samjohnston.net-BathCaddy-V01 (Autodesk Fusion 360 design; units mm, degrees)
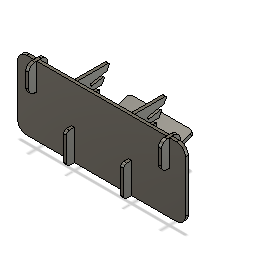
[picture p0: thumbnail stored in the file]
sketch "Sketch1" plane through (0, 0, 0) normal (0, 0, 1) x axis (1, 0, 0)
  line L1 (-340, 0) -> (0, 0)
  line L2 (-340, 280) -> (-340, 0)
  line L3 (0, 280) -> (-340, 280)
  line L4 (0, 0) -> (0, 280)
  line L5 (-122, 60) -> (-122, 0)
  line L6 (-110, 60) -> (-122, 60)
  line L7 (-110, 0) -> (-110, 60)
  line L8 (-275, 250) -> (-275, 280)
  line L9 (-263, 250) -> (-275, 250)
  line L10 (-263, 280) -> (-263, 250)
  line L11 (-275, 220) -> (-275, 250)
  line L12 (-263, 220) -> (-275, 220)
  line L13 (-263, 250) -> (-263, 220)
  line L14 (-134, 141.0354) -> (-328, 141.0354)
  line L15 (-134, 12) -> (-134, 141.0354)
  line L16 (-328, 12) -> (-134, 12)
  line L17 (-328, 141.0354) -> (-328, 12)
  line L18 (-340, 141.0354) -> (-328, 141.0354)
  line L19 (-109.5, 0) -> (-110, 3)
  line L20 (-122.5, 0) -> (-122, 3)
  line L21 (-122, 3) -> (-110, 3)
  line L22 (-263, 277) -> (-262.5, 280)
  line L23 (-275.5, 280) -> (-275, 277)
  line L24 (-263, 277) -> (-275, 277)
  line L25 (-269, 141.0354) -> (-269, 220)
  circle C1 centre (-269, 177.0354) radius 40
  point P1 (0, 0)
  point P2 (0, 0)
  point P6 (-122, 0)
  point P9 (-110, 0)
  point P10 (-275, 280)
  point P13 (-263, 280)
  point P21 (-340, 141.0354)
  point P22 (-110, 3)
  point P23 (-109.5, 0)
  point P24 (-122, 3)
  point P25 (-122.5, 0)
  point P26 (-262.5, 280)
  point P27 (-263, 277)
  point P28 (-275, 277)
  point P29 (-275.5, 280)
  point P30 (-269, 220)
  point P31 (-269, 141.0354)
  point P20 (-269, 177.0354)
  point P4 (-340, 280)
  point P5 (0, 280)
  point P3 (-340, 0)
  point P7 (-122, 60)
  point P8 (-110, 60)
  point P11 (-275, 250)
  point P12 (-263, 250)
  point P14 (-275, 220)
  point P16 (-328, 141.0354)
  point P19 (-328, 12)
  horizontal L1
  vertical L2
  horizontal L3
  vertical L4
  coincident P1 P2
  coincident L1 P6
  perpendicular L1 L5
  perpendicular L5 L6
  coincident L1 P9
  perpendicular L1 L7
  coincident L3 P10
  perpendicular L3 L8
  perpendicular L8 L9
  coincident L3 P13
  perpendicular L3 L10
  perpendicular L9 L11
  perpendicular L8 L12
  vertical L13
  horizontal L14
  vertical L15
  horizontal L16
  vertical L17
  coincident L2 P21
  horizontal L18
  coincident L7 P22
  coincident L1 P23
  coincident L5 P24
  coincident L1 P25
  coincident L3 P26
  coincident L10 P27
  coincident L8 P28
  coincident L3 P29
  perpendicular L8 L24
  horizontal L21
  midpoint L12 P30
  coincident L14 P31
  perpendicular L14 L25
  coincident P20 L25
  dimension "d1" distance P4 P5 = 340
  dimension "d2" distance P3 P4 = 280
  dimension "d4" distance P7 P8 = 12
  dimension "d5" distance P8 P9 = 60
  dimension "d7" distance P11 P12 = 12
  dimension "d8" distance P10 P11 = 30
  dimension "d9" distance L4 L8 = 275
  dimension "d10" distance L4 L7 = 110
  dimension "d11" distance P11 P14 = 30
  dimension "d12" distance L2 L17 = 12
  dimension "d14" distance L1 L16 = 12
  dimension "d15" distance L5 L15 = 12
  dimension "d74" diameter C1 = 80
  dimension "d83" distance L10 P26 = 0.5
  dimension "d84" distance P10 P29 = 0.5
  dimension "d85" distance L3 L24 = 3
  dimension "d86" distance L7 P23 = 0.5
  dimension "d87" distance P6 P25 = 0.5
  dimension "d88" distance L1 L21 = 3
  dimension "d108" distance P16 P19 = 129.0354
  dimension "d109" distance L14 P20 = 36
extrude "Extrude1" new body sketch "Sketch1" profile of L1 L2 L3 L4 L5 L6 L7 L8 L9 L10 L11 L12 L13 L14 L15 L16 L17 C1 L18 L19 L20 L22 L23 along normal blind 12 bodies "Platform"
extrude "Extrude8" add sketch "Sketch1" profile of L14 L15 L16 L17 C1 to an object from offset 2
fillet "Fillet1" radius 24 bodies "DeviceHolder1"
fillet "Fillet2" radius 36 bodies "DeviceHolder1"
sketch "Sketch3" plane through (0, 0, 0) normal (1, 0, 0) x axis (0, 0, -1)
  line L1 (0, 3) -> (0, 60)
  line L2 (0, 60) -> (-12, 60)
  line L3 (0, 250) -> (0, 277)
  line L4 (-12, 250) -> (0, 250)
  line L5 (-12, 277) -> (-12, 250)
  line L6 (0, 190) -> (0, 250)
  line L7 (32, 220) -> (0, 220)
  line L8 (32, 280) -> (32, 220)
  line L9 (0, 280) -> (32, 280)
  line L10 (-12, 60) -> (-12, 250)
  line L11 (-44, 172) -> (-12, 172)
  line L12 (-44, 280) -> (-44, 172)
  line L13 (-12, 280) -> (-44, 280)
  line L14 (0, 225) -> (0.5, 220)
  line L15 (-12, 177) -> (-12.5, 172)
  line L16 (-12, 3) -> (0, 3)
  line L17 (0, 277) -> (-12, 277)
  line L18 (-12, 280) -> (0, 280)
  line L19 (0, 280) -> (0, 0)
  point P7 (0, 250)
  point P10 (0, 250)
  point P8 (-12, 250)
  point P15 (-12, 250)
  point P5 (-12, 60)
  point P16 (-12, 60)
  point P21 (0.5, 220)
  point P23 (-12.5, 172)
  point P14 (0, 280)
  point P25 (0, 280)
  point P24 (-12, 177)
  point P17 (-12, 172)
  point P11 (0, 220)
  point P22 (0, 225)
  point P30 (0, 220)
  point P13 (32, 280)
  point P19 (-44, 280)
  point P20 (-12, 280)
  coincident P7 P10
  perpendicular L4 L6
  perpendicular L6 L7
  coincident P8 P15
  coincident P5 P16
  perpendicular L11 L12
  horizontal L13
  horizontal L9
  vertical L8
  coincident L7 P21
  coincident L11 P23
  coincident P14 P25
  coincident L10 P24
  coincident L10 P17
  horizontal L11
  coincident P11 L19
  coincident P22 L19
  coincident P11 P30
  dimension "d25" distance P13 P14 = 32
  dimension "d26" distance P19 P20 = 32
  dimension "d75" distance P17 P23 = 0.5
  dimension "d77" distance P11 P21 = 0.5
  dimension "d78" distance L7 P22 = 5
  dimension "d110" distance L11 P24 = 5
  dimension "d111" distance L7 L11 = 48
extrude "Extrude2" sketch "Sketch3" profile of L3 L4 L5 L6 L7 L8 L9 L10 L11 L12 L13 L14 L15 L17 L18 L19 blind -12 bodies "EndStop1"
fillet "Fillet3" radius 24 bodies "DeviceHolder1"
fillet "Fillet9" radius 2 bodies "DeviceHolder1"
sketch "Sketch4" plane through (0, 0, 0) normal (1, 0, 0) x axis (0, 0, -1)
  line L1 (0, 3) -> (0, 60)
  line L2 (-12, 60) -> (-12, 0)
  line L3 (0, 60) -> (-12, 60)
  line L4 (24, 0) -> (0, 0)
  line L5 (65.4939, 96.4469) -> (74.9501, 89.0589)
  line L6 (40.7734, 64.806) -> (65.4939, 96.4469)
  line L7 (24, 75.6988) -> (40.7734, 64.806)
  line L8 (132.6289, 280) -> (24, 75.6988)
  line L9 (0, 280) -> (132.6289, 280)
  line L10 (0, 60) -> (0, 280)
  line L11 (-44, 0) -> (-12, 0)
  line L12 (-44, 124) -> (-44, 0)
  line L13 (-12, 124) -> (-44, 124)
  line L14 (-12, 60) -> (-12, 124)
  line L15 (49.6788, 14.8256) -> (74.9501, 89.0589)
  line L16 (24, 0) -> (49.6788, 14.8256)
  line L17 (33.4184, 206.2559) -> (93.4184, 206.2559)
  line L18 (33.4184, 217.2559) -> (33.4184, 206.2559)
  line L19 (99.2672, 217.2559) -> (33.4184, 217.2559)
  line L20 (54.2259, 233.2559) -> (113.3144, 243.6748)
  line L21 (52.3158, 244.0888) -> (54.2259, 233.2559)
  line L22 (119.8678, 256) -> (52.3158, 244.0888)
  line L23 (16.5323, 179.2977) -> (76.304, 174.0684)
  line L24 (17.4911, 190.2559) -> (16.5323, 179.2977)
  line L25 (81.9142, 184.6196) -> (17.4911, 190.2559)
  line L26 (28.1042, 24) -> (56.295, 34.2606)
  line L27 (24, 35.2763) -> (28.1042, 24)
  line L28 (61.2572, 48.8368) -> (24, 35.2763)
  line L29 (56.2123, 34.0177) -> (28.1042, 24)
  line L30 (61.3399, 49.0798) -> (24, 35.2763)
  line L31 (24, 75.6988) -> (24, 0)
  line L32 (-12.5, 124) -> (-12, 121)
  line L33 (0, 277) -> (0.5, 280)
  line L34 (-12, 3) -> (0, 3)
  line L35 (0, 0) -> (-12, 0)
  line L36 (0, 3) -> (0, 0)
  point P2 (0, 60)
  point P14 (0, 60)
  point P5 (-12, 60)
  point P19 (-12, 60)
  point P21 (93.4184, 206.2559)
  point P24 (99.2672, 217.2559)
  point P25 (113.3144, 243.6748)
  point P28 (119.8678, 256)
  point P29 (76.304, 174.0684)
  point P32 (81.9142, 184.6196)
  point P33 (56.295, 34.2606)
  point P36 (61.2572, 48.8368)
  point P37 (56.2123, 34.0177)
  point P38 (61.3399, 49.0798)
  point P35 (24, 35.2763)
  point P13 (0, 280)
  point P39 (0, 280)
  point P40 (-12, 121)
  point P41 (-12.5, 124)
  point P42 (0.5, 280)
  point P43 (0, 277)
  point P1 (0, 0)
  point P6 (0, 0)
  point P44 (0, 0)
  point P3 (0, 3)
  point P45 (0, 3)
  point P10 (40.7734, 64.806)
  point P11 (24, 75.6988)
  point P8 (74.9501, 89.0589)
  point P9 (65.4939, 96.4469)
  point P30 (16.5323, 179.2977)
  point P31 (17.4911, 190.2559)
  point P22 (33.4184, 206.2559)
  point P23 (33.4184, 217.2559)
  point P26 (54.2259, 233.2559)
  point P27 (52.3158, 244.0888)
  point P15 (-12, 0)
  point P16 (-44, 0)
  point P18 (-12, 124)
  point P34 (28.1042, 24)
  point P20 (49.6788, 14.8256)
  perpendicular L5 L6
  parallel L3 L9
  coincident P2 P14
  perpendicular L3 L10
  perpendicular L2 L11
  perpendicular L11 L12
  perpendicular L2 L13
  coincident P5 P19
  perpendicular L3 L14
  horizontal L4
  coincident L8 P21
  horizontal L17
  perpendicular L17 L18
  coincident L8 P24
  perpendicular L18 L19
  coincident L8 P25
  perpendicular L20 L21
  coincident L8 P28
  perpendicular L21 L22
  coincident L8 P29
  perpendicular L23 L24
  coincident L8 P32
  perpendicular L24 L25
  coincident L15 P33
  perpendicular L26 L27
  coincident L15 P36
  perpendicular L27 L28
  coincident L15 P37
  coincident L15 P38
  vertical L31
  coincident P35 L31
  coincident P13 P39
  coincident L14 P40
  coincident L13 P41
  coincident L9 P42
  coincident L10 P43
  coincident P1 P6
  coincident P1 P44
  horizontal L35
  coincident P3 P45
  dimension "d33" distance P10 P11 = 20
  dimension "d34" angle L6 L7 = 95
  dimension "d35" angle L7 L8 = 95
  dimension "d36" angle L8 L10 = 28
  dimension "d38" distance P8 P9 = 12
  dimension "d39" distance P9 L7 = 40
  dimension "d40" distance L1 P11 = 24
  dimension "d41" angle L17 L25 = 5
  dimension "d42" angle L19 L20 = 10
  dimension "d43" distance P30 P31 = 11
  dimension "d44" distance P22 P23 = 11
  dimension "d45" distance P26 P27 = 11
  dimension "d46" distance P21 P22 = 60
  dimension "d47" distance P29 P30 = 60
  dimension "d48" distance P25 P26 = 60
  dimension "d49" distance L17 P31 = 16
  dimension "d50" distance L19 P26 = 16
  dimension "d51" distance P15 P16 = 32
  dimension "d52" distance P18 P19 = 64
  dimension "d54" distance L26 P37 = 0.2
  dimension "d55" distance L28 P38 = 0.2
  dimension "d56" distance P34 P35 = 12
  dimension "d59" angle L28 L31 = 70
  dimension "d60" distance P20 L26 = 16
  dimension "d61" angle L16 L31 = 60
  dimension "d62" distance P33 P34 = 30
  dimension "d63" distance L4 P34 = 24
  dimension "d64" distance L9 P28 = 24
  dimension "d79" distance L10 P42 = 0.5
  dimension "d80" distance L14 P41 = 0.5
  dimension "d81" distance L13 P40 = 3
  dimension "d82" distance P42 P43 = 3
extrude "Extrude3" sketch "Sketch4" profile of L1 L2 L3 L4 L5 L6 L7 L8 L9 L10 L11 L12 L13 L14 L15 L16 L17 L18 L19 L20 L21 L22 L23 L24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 blind -12 bodies "DeviceHolder1"
fillet "Fillet4" radius 12 bodies "DeviceHolder1"
fillet "Fillet5" radius 5 bodies "DeviceHolder1"
fillet "Fillet6" radius 4 bodies "DeviceHolder1"
sketch "Sketch5" plane through (0, 0, 0) normal (1, 0, 0) x axis (0, 0, -1)
  line L1 (28.1042, 24) -> (56.295, 34.2606)
  line L2 (61.2572, 48.8368) -> (24, 35.2763)
  line L3 (28.1042, 24) -> (24, 35.2763)
  line L4 (234.8366, 99.2444) -> (56.295, 34.2606)
  line L5 (230.7324, 110.5207) -> (234.8366, 99.2444)
  line L6 (61.2572, 48.8368) -> (230.7324, 110.5207)
  line L7 (83.9952, -30.1498) -> (50.4772, 61.9401)
  line L8 (72.7189, -34.254) -> (83.9952, -30.1498)
  line L9 (39.2009, 57.8358) -> (72.7189, -34.254)
  line L10 (50.4772, 61.9401) -> (39.2009, 57.8358)
  point P4 (24, 35.2763)
  point P6 (24, 35.2763)
  point P3 (28.1042, 24)
  point P7 (28.1042, 24)
  point P2 (56.295, 34.2606)
  point P8 (56.295, 34.2606)
  point P5 (61.2572, 48.8368)
  point P11 (61.2572, 48.8368)
  point P12 (50.4772, 61.9401)
  point P15 (39.2009, 57.8358)
  coincident P4 P6
  coincident P3 P7
  coincident P2 P8
  perpendicular L3 L4
  perpendicular L1 L5
  coincident P5 P11
  collinear L2 L6
  perpendicular L6 L7
  perpendicular L7 L8
  perpendicular L2 L9
  perpendicular L9 L10
  dimension "d89" distance L3 L5 = 220
  dimension "d90" distance P12 P15 = 12
  dimension "d91" distance L3 L9 = 22
  dimension "d92" distance L2 L10 = 16
  dimension "d93" distance L4 L8 = 70
extrude "Extrude4" new body sketch "Sketch5" profile of L1 L2 L3 L4 L5 L6 L7 L9 against normal blind 130
extrude "Extrude5" cut sketch "Sketch5" profile of L2 L4 L6 L7 L9 against normal blind 60
extrude "Extrude6" new body sketch "Sketch5" profile of L2 L4 L6 L7 L9 L10 to an object bodies "BookPlatformLip"
extrude "Extrude7" new body sketch "Sketch5" profile of L1 L4 L7 L8 L9 against normal blind 100
mirror "Mirror1" mirrorStitchTolerance 0.1 bodies "EndStop2", "DeviceHolder2", "BookPlatform"
combine "Combine1"
combine "Combine2"
combine "Combine3"
fillet "Fillet7" radius 12 bodies "DeviceHolder1"
fillet "Fillet8" radius 4 bodies "DeviceHolder1"
sketch "BB-Platform-V01" plane through (0, 0, 0) normal (0, 0, -1) x axis (-1, 0, 0)
  line L1 (-304, 12) -> (-158, 12)
  line L2 (-328, 117.0354) -> (-328, 36)
  line L3 (-158, 141.0354) -> (-244.3423, 141.0354)
  line L4 (-134, 36) -> (-134, 117.0354)
  line L5 (134, 117.0354) -> (134, 36)
  line L6 (304, 141.0354) -> (293.6577, 141.0354)
  line L7 (328, 36) -> (328, 117.0354)
  line L8 (158, 12) -> (304, 12)
  line L9 (275.5, 280) -> (304, 280)
  line L10 (275, 277) -> (275.5, 280)
  line L11 (275, 250) -> (275, 277)
  line L12 (263, 250) -> (275, 250)
  line L13 (263, 277) -> (263, 250)
  line L14 (262.5, 280) -> (263, 277)
  line L15 (-262.5, 280) -> (262.5, 280)
  line L16 (-263, 277) -> (-262.5, 280)
  line L17 (-263, 250) -> (-263, 277)
  line L18 (-275, 250) -> (-263, 250)
  line L19 (-275, 277) -> (-275, 250)
  line L20 (-275.5, 280) -> (-275, 277)
  line L21 (-304, 280) -> (-275.5, 280)
  line L22 (-340, 36) -> (-340, 244)
  line L23 (-122.5, 0) -> (-304, 0)
  line L24 (-122, 3) -> (-122.5, 0)
  line L25 (-122, 60) -> (-122, 3)
  line L26 (-110, 60) -> (-122, 60)
  line L27 (-110, 3) -> (-110, 60)
  line L28 (-109.5, 0) -> (-110, 3)
  line L29 (109.5, 0) -> (-109.5, 0)
  line L30 (110, 3) -> (109.5, 0)
  line L31 (110, 60) -> (110, 3)
  line L32 (122, 60) -> (110, 60)
  line L33 (122, 3) -> (122, 60)
  line L34 (122.5, 0) -> (122, 3)
  line L35 (304, 0) -> (122.5, 0)
  line L36 (340, 244) -> (340, 36)
  line L37 (-293.6577, 141.0354) -> (-304, 141.0354)
  line L38 (244.3423, 141.0354) -> (158, 141.0354)
  arc A1 centre (-158, 36) radius 24 clockwise from (-134, 36) to (-158, 12)
  arc A2 centre (-304, 36) radius 24 clockwise from (-304, 12) to (-328, 36)
  arc A3 centre (-304, 117.0354) radius 24 clockwise from (-328, 117.0354) to (-304, 141.0354)
  arc A4 centre (-158, 117.0354) radius 24 clockwise from (-158, 141.0354) to (-134, 117.0354)
  arc A5 centre (158, 36) radius 24 clockwise from (158, 12) to (134, 36)
  arc A6 centre (158, 117.0354) radius 24 clockwise from (134, 117.0354) to (158, 141.0354)
  arc A7 centre (304, 117.0354) radius 24 clockwise from (304, 141.0354) to (328, 117.0354)
  arc A8 centre (304, 36) radius 24 clockwise from (328, 36) to (304, 12)
  arc A9 centre (304, 244) radius 36 clockwise from (304, 280) to (340, 244)
  arc A10 centre (-304, 244) radius 36 clockwise from (-340, 244) to (-304, 280)
  arc A11 centre (-304, 36) radius 36 clockwise from (-304, 0) to (-340, 36)
  arc A12 centre (304, 36) radius 36 clockwise from (340, 36) to (304, 0)
  arc A13 centre (-269, 177.0354) radius 40 clockwise from (-292.4835, 144.6544) to (-245.5165, 144.6544)
  arc A14 centre (269, 177.0354) radius 40 clockwise from (245.5165, 144.6544) to (292.4835, 144.6544)
  arc A15 centre (-293.6577, 143.0354) radius 2 clockwise from (-292.4835, 144.6544) to (-293.6577, 141.0354)
  arc A16 centre (-244.3423, 143.0354) radius 2 clockwise from (-244.3423, 141.0354) to (-245.5165, 144.6544)
  arc A17 centre (293.6577, 143.0354) radius 2 clockwise from (293.6577, 141.0354) to (292.4835, 144.6544)
  arc A18 centre (244.3423, 143.0354) radius 2 clockwise from (245.5165, 144.6544) to (244.3423, 141.0354)
sketch "BB-Stop-V01" plane through (275, 0, 0) normal (1, 0, 0) x axis (0, 0, -1)
  line L1 (0, 225) -> (0, 250)
  line L2 (8, 220) -> (0.5, 220)
  line L3 (0.5, 220) -> (0, 225)
  line L4 (0, 250) -> (-12, 250)
  line L5 (32, 256) -> (32, 244)
  line L6 (-20, 280) -> (8, 280)
  line L7 (-12, 172) -> (-20, 172)
  line L8 (-12, 250) -> (-12, 172)
  line L9 (-44, 196) -> (-44, 256)
  arc A1 centre (8, 244) radius 24 clockwise from (32, 244) to (8, 220)
  arc A2 centre (8, 256) radius 24 clockwise from (8, 280) to (32, 256)
  arc A3 centre (-20, 196) radius 24 clockwise from (-20, 172) to (-44, 196)
  arc A4 centre (-20, 256) radius 24 clockwise from (-44, 256) to (-20, 280)
sketch "BB-Holder-V01" plane through (122, 0, 0) normal (1, 0, 0) x axis (0, 0, -1)
  line L1 (0.5, 280) -> (125.9717, 280)
  line L2 (0, 277) -> (0.5, 280)
  line L3 (0, 60) -> (0, 277)
  line L4 (-12, 60) -> (0, 60)
  line L5 (-12, 121) -> (-12, 60)
  line L6 (-12.5, 124) -> (-12, 121)
  line L7 (-32, 124) -> (-12.5, 124)
  line L8 (-44, 12) -> (-44, 112)
  line L9 (20.7846, 0) -> (-32, 0)
  line L10 (45.7726, 12.5704) -> (26.7846, 1.6077)
  line L11 (53.5448, 26.1819) -> (51.1323, 19.0955)
  line L12 (28.1042, 24) -> (48.4153, 31.2388)
  line L13 (24, 35.2763) -> (28.1042, 24)
  line L14 (59.5539, 48.4195) -> (24, 35.2763)
  line L15 (74.034, 86.3679) -> (61.9536, 50.8823)
  line L16 (68.646, 93.9842) -> (72.71, 90.8091)
  line L17 (43.5942, 68.4164) -> (63.0313, 93.2948)
  line L18 (27.8425, 73.2035) -> (36.9309, 67.3014)
  line L19 (73.4668, 168.7324) -> (26.151, 79.7442)
  line L20 (20.5171, 178.9491) -> (70.2837, 174.5951)
  line L21 (17.1424, 186.2711) -> (16.881, 183.2825)
  line L22 (79.2767, 184.8503) -> (21.4758, 189.9072)
  line L23 (90.2931, 200.378) -> (83.1571, 186.9572)
  line L24 (37.4184, 206.2559) -> (86.7613, 206.2559)
  line L25 (33.4184, 213.2559) -> (33.4184, 210.2559)
  line L26 (96.8638, 217.2559) -> (37.4184, 217.2559)
  line L27 (109.4642, 236.4335) -> (100.3956, 219.378)
  line L28 (58.1652, 233.9505) -> (105.2378, 242.2506)
  line L29 (53.0104, 240.1495) -> (53.5313, 237.1951)
  line L30 (117.9465, 255.6612) -> (56.255, 244.7833)
  line L31 (129.5035, 274.1221) -> (120.7837, 257.7226)
  arc A1 centre (125.9717, 276) radius 4 clockwise from (125.9717, 280) to (129.5035, 274.1221)
  arc A2 centre (-32, 112) radius 12 clockwise from (-44, 112) to (-32, 124)
  arc A3 centre (-32, 12) radius 12 clockwise from (-32, 0) to (-44, 12)
  arc A4 centre (20.7846, 12) radius 12 clockwise from (26.7846, 1.6077) to (20.7846, 0)
  arc A5 centre (39.7726, 22.9627) radius 12 clockwise from (51.1323, 19.0955) to (45.7726, 12.5704)
  arc A6 centre (49.7582, 27.471) radius 4 clockwise from (48.4153, 31.2388) to (53.5448, 26.1819)
  arc A7 centre (58.167, 52.1714) radius 4 clockwise from (61.9536, 50.8823) to (59.5539, 48.4195)
  arc A8 centre (70.2474, 87.657) radius 4 clockwise from (72.71, 90.8091) to (74.034, 86.3679)
  arc A9 centre (66.1833, 90.8322) radius 4 clockwise from (63.0313, 93.2948) to (68.646, 93.9842)
  arc A10 centre (39.6541, 71.4947) radius 5 clockwise from (43.5942, 68.4164) to (36.9309, 67.3014)
  arc A11 centre (30.5657, 77.3968) radius 5 clockwise from (27.8425, 73.2035) to (26.151, 79.7442)
  arc A12 centre (69.9351, 170.6103) radius 4 clockwise from (70.2837, 174.5951) to (73.4668, 168.7324)
  arc A13 centre (20.8657, 182.9339) radius 4 clockwise from (20.5171, 178.9491) to (16.881, 183.2825)
  arc A14 centre (21.1272, 185.9225) radius 4 clockwise from (17.1424, 186.2711) to (21.4758, 189.9072)
  arc A15 centre (79.6253, 188.8351) radius 4 clockwise from (83.1571, 186.9572) to (79.2767, 184.8503)
  arc A16 centre (86.7613, 202.2559) radius 4 clockwise from (86.7613, 206.2559) to (90.2931, 200.378)
  arc A17 centre (37.4184, 210.2559) radius 4 clockwise from (37.4184, 206.2559) to (33.4184, 210.2559)
  arc A18 centre (37.4184, 213.2559) radius 4 clockwise from (33.4184, 213.2559) to (37.4184, 217.2559)
  arc A19 centre (96.8638, 221.2559) radius 4 clockwise from (100.3956, 219.378) to (96.8638, 217.2559)
  arc A20 centre (105.9324, 238.3114) radius 4 clockwise from (105.2378, 242.2506) to (109.4642, 236.4335)
  arc A21 centre (57.4706, 237.8897) radius 4 clockwise from (58.1652, 233.9505) to (53.5313, 237.1951)
  arc A22 centre (56.9496, 240.8441) radius 4 clockwise from (53.0104, 240.1495) to (56.255, 244.7833)
  arc A23 centre (117.252, 259.6005) radius 4 clockwise from (120.7837, 257.7226) to (117.9465, 255.6612)
sketch "BB-Book-V01" plane through (0, 12.16, 4.4259) normal (0, -0.9397, -0.342) x axis (-1, 0, 0)
  line L1 (130, 242.6178) -> (130, 38.6178)
  line L2 (-118, 254.6178) -> (118, 254.6178)
  line L3 (-130, 38.6178) -> (-130, 242.6178)
  line L4 (126, 34.6178) -> (-126, 34.6178)
  line L5 (-60, 56.6178) -> (60, 56.6178)
  line L6 (-60, 68.6178) -> (-60, 56.6178)
  line L7 (60, 68.6178) -> (-60, 68.6178)
  line L8 (60, 56.6178) -> (60, 68.6178)
  arc A1 centre (126, 38.6178) radius 4 clockwise from (130, 38.6178) to (126, 34.6178)
  arc A2 centre (118, 242.6178) radius 12 clockwise from (118, 254.6178) to (130, 242.6178)
  arc A3 centre (-118, 242.6178) radius 12 clockwise from (-130, 242.6178) to (-118, 254.6178)
  arc A4 centre (-126, 38.6178) radius 4 clockwise from (-126, 34.6178) to (-130, 38.6178)
sketch "BB-Lip-V01" plane through (0, 23.4687, -64.4797) normal (0, 0.342, -0.9397) x axis (-1, 0, 0)
  line L1 (-60, 12.9404) -> (-60, 28.9404)
  line L2 (-100, 12.9404) -> (-60, 12.9404)
  line L3 (-100, -45.0596) -> (-100, 12.9404)
  line L4 (88, -57.0596) -> (-88, -57.0596)
  line L5 (100, 12.9404) -> (100, -45.0596)
  line L6 (60, 12.9404) -> (100, 12.9404)
  line L7 (60, 28.9404) -> (60, 12.9404)
  line L8 (-48, 40.9404) -> (48, 40.9404)
  arc A1 centre (-48, 28.9404) radius 12 clockwise from (-60, 28.9404) to (-48, 40.9404)
  arc A2 centre (-88, -45.0596) radius 12 clockwise from (-88, -57.0596) to (-100, -45.0596)
  arc A3 centre (88, -45.0596) radius 12 clockwise from (100, -45.0596) to (88, -57.0596)
  arc A4 centre (48, 28.9404) radius 12 clockwise from (48, 40.9404) to (60, 28.9404)
named bodies: "Platform", "EndStop1", "DeviceHolder1", "BookPlatformLip", "EndStop2", "DeviceHolder2", "BookPlatform"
